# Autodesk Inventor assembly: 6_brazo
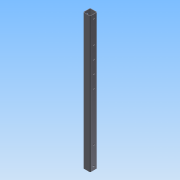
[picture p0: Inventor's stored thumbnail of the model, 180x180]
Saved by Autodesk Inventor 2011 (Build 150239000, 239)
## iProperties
Created: 2020-12
Part Number: 6_brazo
Document SubType Name: Assembly
Designer: PC
Mass: 7482.69 g
Surface Area: 4801.2 cm^2
Volume: 951.996 cm^3
Density: 7.86 g/cm^3
Author: PC
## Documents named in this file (2)
- C:\Users\PC\Documents\Inventor\workshop-crane-powered-by-drill\6_brazo.iam
- C:\Users\PC\Documents\Inventor\workshop-crane-powered-by-drill\DIN EN 10219-2 - 60 x 60 x 4  - 1125.ipt
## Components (1 placed, 1 different names)
1. DIN EN 10219-2 - 60 x 60 x 4  - 1125:1
